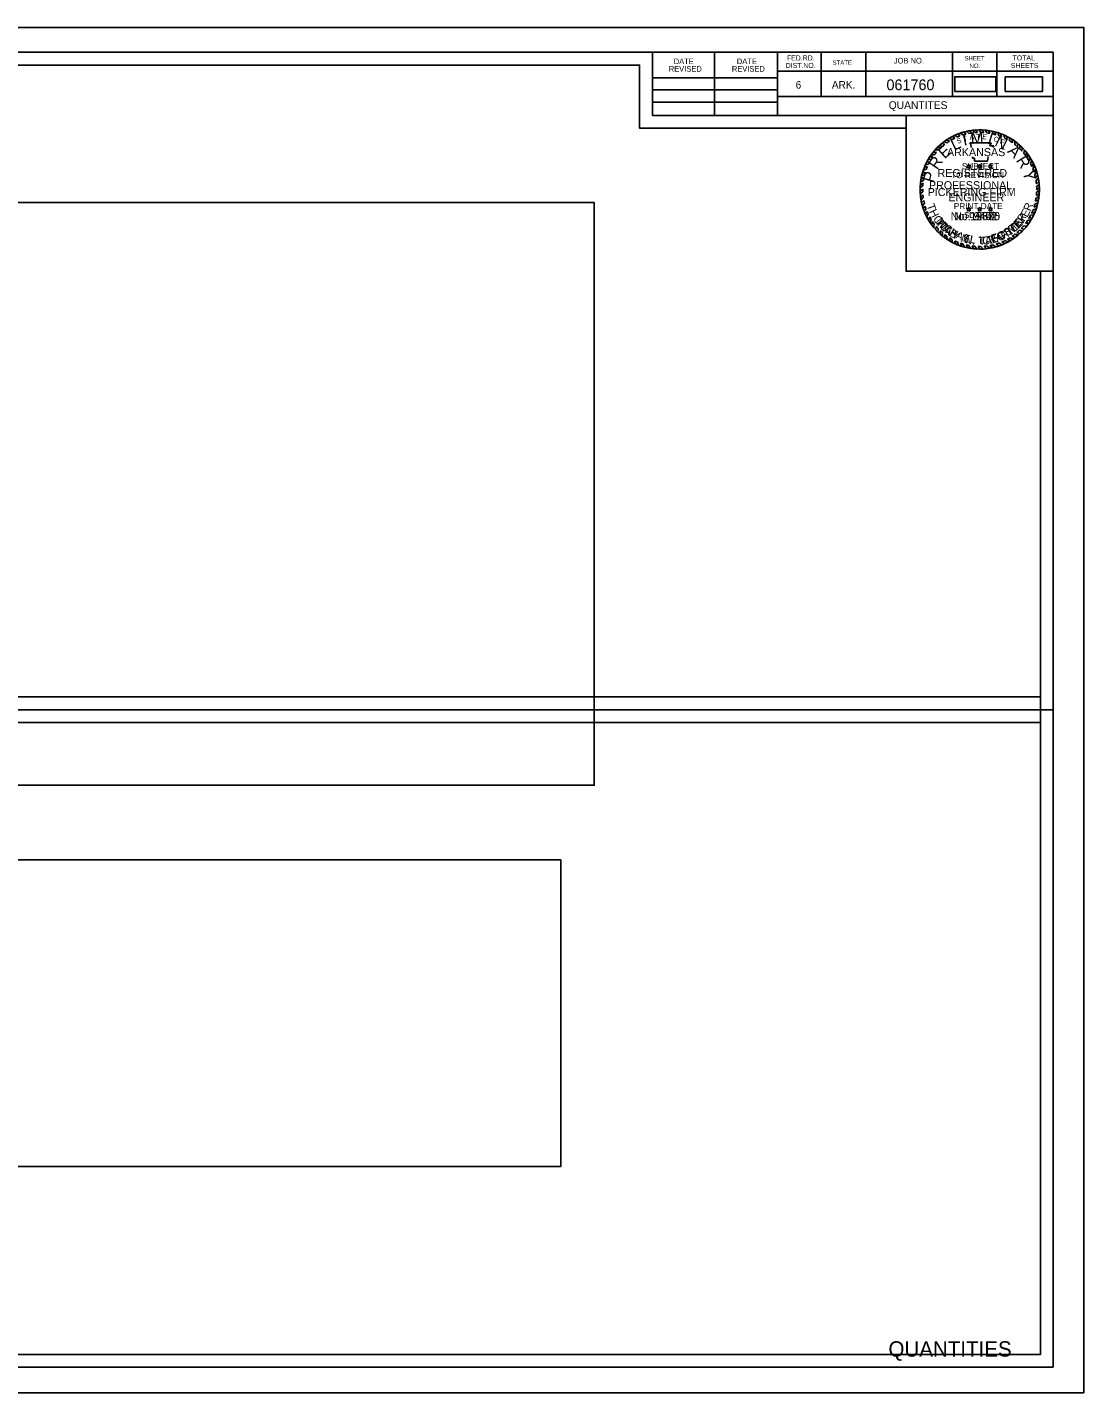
# Model space of a CAD drawing. Extents: x 365 to 1553, y -4 to 209.
# Drawn here: x 532.8 to 697.9, y -4 to 209.4 of the extents above; entities that cross this region are included whole.
import ezdxf

# ---------------------------------------------------------------- set-up
doc = ezdxf.new("R2010")
doc.units = 0
for name, color, linetype in [('Default', 7, 'Continuous'), ('R_Border', 7, 'Continuous'), ('R_Border Notes', 7, 'Continuous'), ('R_Border Plan-Plan', 7, 'Continuous'), ('R_Border Title', 7, 'Continuous'), ('R_No Plot', 7, 'Continuous'), ('STAMP_PE_CRAFTON', 7, 'Continuous'), ('STAMP_PE_FOSTER', 7, 'Continuous'), ('STAMP_PE_SEAL-INFO', 7, 'Continuous'), ('STAMP_PE_TAEGTMEYER', 7, 'Continuous'), ('STAMP_PE_TXT', 7, 'Continuous'), ('STAMP_PRELIMINARY', 7, 'Continuous')]:
    doc.layers.add(name, color=color, linetype=linetype)

msp = doc.modelspace()

# ---------------------------------------------------------------- linework, layer by layer
at = {"layer": 'Default'}
for points in [[(677.71, 199.3), (684.15, 199.3), (684.15, 201.61), (677.71, 201.61)], [(685.6, 199.3), (691.43, 199.3), (691.43, 201.61), (685.6, 201.61)], [(452.83, 90.94), (621.39, 90.94), (621.39, 181.97), (452.83, 181.97)], [(458.06, 31.38), (616.17, 31.38), (616.17, 79.26), (458.06, 79.26)]]:
    msp.add_lwpolyline(points, close=True, dxfattribs=at)
at = {"layer": 'R_Border'}
for p, q in [((376.94, 205.46), (693.12, 205.46)), ((630.48, 195.58), (630.48, 205.46)), ((640.16, 195.58), (640.16, 205.46)), ((650.02, 205.46), (650.02, 195.58)), ((656.86, 205.46), (656.86, 198.52)), ((663.8, 205.46), (663.8, 198.52)), ((677.38, 205.46), (677.38, 198.52)), ((684.32, 205.46), (684.32, 198.52)), ((693.12, 0), (693.12, 205.46)), ((630.48, 201.44), (650.02, 201.44)), ((693.12, 202.52), (650.02, 202.52)), ((693.12, 202.54), (693.12, 202.54)), ((630.48, 199.58), (650.02, 199.58)), ((693.12, 198.52), (650.02, 198.52)), ((652.98, 198.52), (693.12, 198.52)), ((630.48, 197.64), (650.02, 197.64)), ((693.12, 195.58), (630.48, 195.58)), ((693.12, 0), (376.94, 0))]:
    msp.add_line(p, q, dxfattribs=at)
at = {"layer": 'R_Border Plan-Plan'}
msp.add_line((376.94, 102.73), (693.12, 102.73), dxfattribs=at)
at = {"layer": 'R_No Plot'}
for points in [[(364.53, 209.35), (697.87, 209.35), (697.87, -3.98), (364.53, -3.98)], [(691.12, 104.73), (378.94, 104.73), (378.94, 203.46), (628.48, 203.46), (628.48, 193.58), (646.02, 193.58), (670.12, 193.58), (670.12, 171.25), (691.12, 171.25)], [(378.94, 203.46), (628.48, 203.46), (628.48, 193.58), (646.02, 193.58), (670.12, 193.58), (670.12, 171.25), (691.12, 171.25), (691.12, 2), (378.94, 2)], [(670.12, 195.58), (693.12, 195.58), (693.12, 171.25), (670.12, 171.25)], [(378.94, 100.73), (691.12, 100.73), (691.12, 2), (378.94, 2)]]:
    msp.add_lwpolyline(points, close=True, dxfattribs=at)
at = {"layer": 'STAMP_PE_SEAL-INFO'}
for p, q in [((676.84, 192.03), (677.27, 191.81)), ((677.29, 192.28), (677.75, 192.06)), ((677.72, 192.49), (678.11, 192.22)), ((678.23, 192.71), (678.52, 192.38)), ((678.58, 192.84), (678.96, 192.53)), ((679.17, 193.02), (679.45, 192.67)), ((679.55, 193.11), (679.91, 192.77)), ((680.04, 193.21), (680.34, 192.84)), ((680.55, 193.28), (680.83, 192.9)), ((681.29, 192.93), (680.98, 193.32)), ((681.79, 192.93), (681.51, 193.34)), ((682.24, 192.91), (681.99, 193.34)), ((682.75, 192.86), (682.46, 193.31)), ((683.18, 192.8), (682.92, 193.25)), ((683.74, 192.68), (683.56, 193.14)), ((684.14, 192.57), (683.98, 193.04)), ((684.59, 192.42), (684.45, 192.9)), ((685.01, 192.26), (684.87, 192.76)), ((685.47, 192.06), (685.37, 192.56)), ((685.92, 191.83), (685.83, 192.34)), ((686.3, 191.6), (686.26, 192.1)), ((674.66, 190.22), (675.18, 190.19)), ((674.98, 190.57), (675.52, 190.53)), ((675.31, 190.89), (675.77, 190.75)), ((675.66, 191.19), (676.19, 191.09)), ((676.03, 191.52), (676.49, 191.31)), ((676.45, 191.79), (676.9, 191.58)), ((680.09, 191.31), (683.43, 191.31)), ((680.21, 191.01), (680.09, 191.31)), ((680.31, 190.71), (680.21, 191.01)), ((680.32, 190.59), (680.31, 190.71)), ((683.43, 191.31), (683.21, 190.82)), ((683.21, 190.82), (683.84, 190.82)), ((683.84, 190.82), (683.7, 190.59)), ((686.74, 191.32), (686.71, 191.83)), ((687.1, 191.05), (687.13, 191.54)), ((687.55, 190.68), (687.57, 191.2)), ((687.86, 190.39), (687.93, 190.88)), ((688.22, 190.01), (688.28, 190.54)), ((688.49, 189.7), (688.63, 190.17)), ((673.13, 187.89), (673.63, 187.99)), ((673.32, 188.27), (673.82, 188.34)), ((673.55, 188.7), (674.04, 188.72)), ((673.8, 189.1), (674.31, 189.13)), ((674.03, 189.44), (674.54, 189.44)), ((674.31, 189.81), (674.86, 189.83)), ((680.51, 188.89), (680.49, 189.1)), ((680.83, 188.89), (680.51, 188.89)), ((680.83, 188.46), (680.83, 188.89)), ((682.86, 188.46), (680.83, 188.46)), ((682.87, 188.79), (682.86, 188.46)), ((682.95, 189.1), (682.87, 188.79)), ((688.82, 189.28), (688.95, 189.78)), ((689.04, 188.96), (689.21, 189.43)), ((689.34, 188.47), (689.53, 188.96)), ((689.54, 188.1), (689.77, 188.54)), ((689.77, 187.62), (690, 188.1)), ((672.9, 185.89), (672.44, 185.64)), ((672.54, 186.14), (673.01, 186.33)), ((672.64, 186.54), (673.12, 186.71)), ((672.8, 187.05), (673.28, 187.18)), ((672.95, 187.45), (673.45, 187.6)), ((689.91, 187.28), (690.18, 187.71)), ((690.11, 186.73), (690.38, 187.2)), ((690.22, 186.37), (690.51, 186.82)), ((690.35, 185.81), (690.67, 186.25)), ((690.42, 185.43), (690.77, 185.78)), ((672.72, 184.57), (672.3, 184.31)), ((672.7, 184.08), (672.3, 183.74)), ((672.76, 185), (672.32, 184.71)), ((672.71, 183.67), (672.32, 183.35)), ((672.82, 185.43), (672.37, 185.21)), ((690.49, 184.92), (690.86, 185.25)), ((690.52, 184.5), (690.91, 184.79)), ((690.52, 183.58), (690.94, 183.85)), ((690.53, 183.98), (690.94, 184.3)), ((672.74, 183.18), (672.37, 182.82)), ((672.8, 182.75), (672.44, 182.37)), ((672.87, 182.29), (672.53, 181.92)), ((672.97, 181.87), (672.66, 181.45)), ((673.09, 181.42), (672.8, 181)), ((690.08, 181.24), (690.57, 181.44)), ((690.23, 181.73), (690.7, 181.93)), ((690.34, 182.18), (690.79, 182.38)), ((690.43, 182.68), (690.87, 182.9)), ((690.48, 183.07), (690.91, 183.33)), ((673.23, 181), (672.95, 180.59)), ((673.4, 180.57), (673.14, 180.15)), ((673.57, 180.19), (673.34, 179.73)), ((673.8, 179.73), (673.61, 179.24)), ((674.04, 179.33), (673.86, 178.86)), ((689.13, 179.23), (689.61, 179.22)), ((689.3, 179.51), (689.8, 179.56)), ((689.57, 180), (690.06, 180.07)), ((689.73, 180.34), (690.22, 180.44)), ((689.95, 180.86), (690.43, 180.99)), ((674.24, 179.01), (674.13, 178.46)), ((674.52, 178.62), (674.42, 178.09)), ((674.83, 178.25), (674.74, 177.73)), ((675.13, 177.91), (675.07, 177.39)), ((675.45, 177.58), (675.42, 177.05)), ((675.8, 177.27), (675.79, 176.74)), ((687.44, 177.27), (687.91, 177.14)), ((687.84, 177.64), (688.28, 177.51)), ((688.1, 177.9), (688.58, 177.82)), ((688.48, 178.34), (688.94, 178.26)), ((688.79, 178.73), (689.29, 178.73)), ((676.16, 176.98), (676.18, 176.45)), ((676.5, 176.73), (676.53, 176.21)), ((676.92, 176.45), (676.98, 175.93)), ((677.27, 176.24), (677.36, 175.73)), ((677.75, 175.99), (677.91, 175.47)), ((678.13, 175.82), (678.3, 175.31)), ((678.62, 175.63), (678.83, 175.13)), ((679.03, 175.49), (679.25, 175)), ((679.54, 175.36), (679.75, 174.89)), ((679.93, 175.27), (680.18, 174.81)), ((680.43, 175.19), (680.67, 174.75)), ((680.87, 175.14), (681.15, 174.71)), ((681.36, 175.11), (681.66, 174.7)), ((681.82, 175.11), (682.16, 174.72)), ((682.33, 175.14), (682.66, 174.76)), ((682.77, 175.18), (683.15, 174.83)), ((683.22, 175.25), (683.61, 174.91)), ((683.71, 175.36), (684.09, 175.03)), ((684.17, 175.48), (684.59, 175.19)), ((684.66, 175.65), (685.1, 175.38)), ((685.08, 175.81), (685.5, 175.55)), ((685.54, 176.02), (686.02, 175.81)), ((685.95, 176.23), (686.37, 176)), ((686.36, 176.48), (686.81, 176.28)), ((686.71, 176.71), (687.15, 176.52)), ((687.17, 177.05), (687.64, 176.9))]:
    msp.add_line(p, q, dxfattribs=at)
for radius, start, end in [(9.32, 117.6544, 120.8099), (8.91, 115.6869, 119.1583), (9.32, 111.3124, 114.7026), (8.91, 110.3086, 113.1659), (9.32, 105.2339, 109.0352), (8.91, 104.0352, 107.3615), (9.32, 99.7525, 102.7765), (8.91, 98.258, 101.0329), (9.32, 93.9381, 96.5517), (8.91, 92.1102, 95.0367), (9.32, 87.7298, 90.6707), (8.91, 85.9628, 88.9097), (9.32, 81.9732, 84.8236), (8.91, 79.9264, 82.696), (9.32, 75.3125, 77.9426), (8.91, 73.5575, 76.2314), (9.32, 69.6061, 72.3058), (8.91, 67.6248, 70.504), (9.32, 63.1329, 66.2704), (8.91, 61.1558, 64.3784), (9.32, 56.9003, 60.0942), (9.32, 135.4021, 138.3031), (8.91, 133.1331, 136.2562), (9.32, 129.7326, 132.5376), (8.91, 127.5297, 130.9683), (9.32, 123.6199, 126.5906), (8.91, 121.9746, 125.11), (8.91, 54.9238, 58.2702), (8.91, 48.3016, 52.0395), (9.32, 50.3492, 53.7159), (8.91, 42.2212, 45.5512), (9.32, 44.3405, 47.3929), (9.32, 38.1247, 41.2316), (9.32, 152.864, 155.5189), (9.32, 147.0072, 149.899), (8.91, 151.0315, 153.573), (9.32, 141.6056, 144.4486), (8.91, 145.0197, 148.2104), (8.91, 139.301, 142.5873), (8.91, 36.135, 39.5311), (8.91, 29.9032, 33.6645), (9.32, 31.9614, 35.4294), (8.91, 23.7732, 27.2211), (9.32, 25.9391, 29.0125), (9.32, 170.0003, 172.6878), (9.32, 164.3068, 166.894), (9.32, 158.4077, 161.0701), (8.91, 167.9048, 170.9039), (8.91, 162.4331, 165.0013), (8.91, 156.3402, 159.2319), (8.91, 17.6802, 21.4251), (9.32, 19.9538, 23.3141), (8.91, 11.5444, 15.2364), (9.32, 13.8421, 17.4447), (9.32, 7.5852, 10.8621), (9.32, 175.7409, 178.2066), (9.32, 181.7251, 184.1626), (8.91, 179.6454, 182.2633), (8.91, 173.73, 176.4734), (8.91, 5.7599, 9.0606), (8.91, 353.8632, 357.1274), (8.91, 359.7329, 3.0639), (9.32, 1.7215, 4.7268), (9.32, 355.7156, 358.9569), (9.32, 187.4204, 190.1927), (9.32, 193.0369, 195.9973), (8.91, 185.4539, 188.234), (8.91, 191.2274, 193.9858), (8.91, 196.9675, 199.8353), (8.91, 341.777, 345.0925), (8.91, 348.0778, 351.3435), (9.32, 343.8925, 347.035), (9.32, 349.8305, 353.0885), (9.32, 198.8967, 201.6281), (9.32, 204.5479, 207.4328), (8.91, 202.7761, 205.4791), (9.32, 210.8636, 213.6571), (8.91, 208.7883, 211.7934), (8.91, 323.5851, 327.4407), (9.32, 325.4405, 328.9872), (8.91, 329.5549, 333.2076), (8.91, 335.6038, 339.1858), (9.32, 331.4037, 334.9332), (9.32, 337.3837, 340.9933), (9.32, 216.6115, 219.491), (8.91, 214.1838, 217.2747), (9.32, 222.48, 225.3801), (8.91, 220.3909, 223.3056), (8.91, 226.2494, 229.2407), (8.91, 310.7744, 314.3161), (9.32, 312.4518, 315.6633), (8.91, 316.6531, 320.3711), (9.32, 318.2846, 321.8043), (9.32, 228.3665, 231.348), (8.91, 232.229, 234.9336), (9.32, 234.295, 236.9452), (8.91, 238.2223, 240.8353), (9.32, 240.1977, 242.8613), (8.91, 244.3204, 246.9486), (9.32, 246.576, 249.1558), (8.91, 250.3491, 253.1216), (9.32, 252.5967, 255.3252), (8.91, 256.505, 259.1192), (8.91, 262.3783, 265.2012), (8.91, 268.3215, 271.277), (8.91, 274.6157, 277.4486), (8.91, 280.3459, 283.5814), (9.32, 282.3199, 285.3702), (8.91, 286.6423, 289.9783), (9.32, 288.5709, 291.9733), (8.91, 292.8745, 296.1185), (9.32, 294.6481, 298.2166), (8.91, 299.0768, 302.1724), (9.32, 300.621, 303.8703), (8.91, 304.823, 308.5143), (9.32, 306.3721, 310.208), (9.32, 258.4433, 261.1398), (9.32, 264.1978, 267.1009), (9.32, 270.2548, 273.3361), (9.32, 276.4239, 279.4357)]:
    msp.add_arc((681.62, 184.02), radius, start, end, dxfattribs=at)
at = {"layer": 'STAMP_PE_TXT'}
for p, q in [((679.8, 187.59), (679.6, 187.74)), ((679.6, 187.74), (679.84, 187.74)), ((679.84, 187.74), (679.92, 187.97)), ((679.92, 187.97), (679.99, 187.74)), ((679.99, 187.74), (680.24, 187.74)), ((680.24, 187.74), (680.04, 187.59)), ((681.49, 187.59), (681.3, 187.74)), ((681.3, 187.74), (681.54, 187.74)), ((681.54, 187.74), (681.62, 187.97)), ((681.62, 187.97), (681.69, 187.74)), ((681.69, 187.74), (681.94, 187.74)), ((681.94, 187.74), (681.74, 187.59)), ((683.19, 187.59), (682.99, 187.74)), ((682.99, 187.74), (683.24, 187.74)), ((683.24, 187.74), (683.31, 187.97)), ((683.31, 187.97), (683.39, 187.74)), ((683.39, 187.74), (683.64, 187.74)), ((683.64, 187.74), (683.44, 187.59)), ((679.72, 187.36), (679.8, 187.59)), ((679.92, 187.5), (679.72, 187.36)), ((680.12, 187.36), (679.92, 187.5)), ((680.04, 187.59), (680.12, 187.36)), ((681.42, 187.36), (681.49, 187.59)), ((681.62, 187.5), (681.42, 187.36)), ((681.82, 187.36), (681.62, 187.5)), ((681.74, 187.59), (681.82, 187.36)), ((683.12, 187.36), (683.19, 187.59)), ((683.31, 187.5), (683.12, 187.36)), ((683.51, 187.36), (683.31, 187.5)), ((683.44, 187.59), (683.51, 187.36)), ((679.8, 180.89), (679.6, 181.03)), ((679.6, 181.03), (679.84, 181.03)), ((679.72, 180.65), (679.8, 180.89)), ((679.92, 180.8), (679.72, 180.65)), ((679.84, 181.03), (679.92, 181.26)), ((679.92, 181.26), (679.99, 181.03)), ((680.12, 180.65), (679.92, 180.8)), ((679.99, 181.03), (680.24, 181.03)), ((680.24, 181.03), (680.04, 180.89)), ((680.04, 180.89), (680.12, 180.65)), ((681.49, 180.89), (681.3, 181.03)), ((681.3, 181.03), (681.54, 181.03)), ((681.42, 180.65), (681.49, 180.89)), ((681.62, 180.8), (681.42, 180.65)), ((681.54, 181.03), (681.62, 181.26)), ((681.62, 181.26), (681.69, 181.03)), ((681.82, 180.65), (681.62, 180.8)), ((681.69, 181.03), (681.94, 181.03)), ((681.94, 181.03), (681.74, 180.89)), ((681.74, 180.89), (681.82, 180.65)), ((683.19, 180.89), (682.99, 181.03)), ((682.99, 181.03), (683.24, 181.03)), ((683.12, 180.65), (683.19, 180.89)), ((683.31, 180.8), (683.12, 180.65)), ((683.24, 181.03), (683.31, 181.26)), ((683.31, 181.26), (683.39, 181.03)), ((683.51, 180.65), (683.31, 180.8)), ((683.39, 181.03), (683.64, 181.03)), ((683.64, 181.03), (683.44, 180.89)), ((683.44, 180.89), (683.51, 180.65))]:
    msp.add_line(p, q, dxfattribs=at)
at = {"layer": 'STAMP_PRELIMINARY'}
msp.add_circle((681.62, 184.02), 9.32, dxfattribs=at)

# ---------------------------------------------------------------- texts
at = {"layer": 'R_Border'}
for s, height, p in [('FED.RD.', 0.782, (651.5, 204.18)), ('SHEET', 0.684, (679.24, 204.18)), ('TOTAL', 0.782, (686.76, 204.18)), ('REVISED', 0.879, (633.03, 202.42)), ('DATE', 0.879, (633.81, 203.6)), ('REVISED', 0.879, (642.89, 202.42)), ('DATE', 0.879, (643.67, 203.6)), ('DIST.NO.', 0.782, (651.3, 203)), ('STATE', 0.684, (658.62, 203.5)), ('JOB NO.', 0.879, (668.2, 203.7)), ('NO.', 0.684, (680.02, 203)), ('SHEETS', 0.782, (686.48, 203)), ('6', 1.17, (652.86, 199.78)), ('ARK.', 1.172, (658.52, 199.78))]:
    msp.add_text(s, height=height, dxfattribs=at).set_placement(p)
at = {"layer": 'R_Border Notes'}
for s, height, p in [('061760', 1.68, (667.05, 199.53)), ('QUANTITES', 1.2, (667.4, 196.6))]:
    msp.add_text(s, height=height, dxfattribs=at).set_placement(p)
at = {"layer": 'R_Border Title'}
msp.add_text('QUANTITIES', height=2.4, dxfattribs=at).set_placement((667.36, 1.65))
at = {"layer": 'STAMP_PE_CRAFTON'}
for s, rotation, p in [('T', 310.7442, (674.58, 178.92)), ('N', 49.2411, (687.9, 178.04)), ('O', 317.6422, (675.25, 178.11)), ('N', 324.4537, (676.1, 177.32)), ('Y', 331.1686, (677.13, 176.61)), ('A', 20.5125, (684.3, 175.78)), ('F', 28.7821, (685.28, 176.15)), ('T', 34.1136, (686.19, 176.66)), ('O', 41.8391, (687.05, 177.26)), ('N', 347.4752, (679.18, 175.69)), ('.', 356.8926, (680.41, 175.41)), ('C', 6.0117, (682.09, 175.36)), ('R', 14.8189, (683.18, 175.48))]:
    msp.add_text(s, height=1.25, rotation=rotation, dxfattribs=at).set_placement(p)
msp.add_text('No. 12370', height=1.25, dxfattribs=at).set_placement((677.08, 179.22))
at = {"layer": 'STAMP_PE_FOSTER'}
for s, rotation, p in [('M', 308.339, (674.73, 179.04)), ('E', 46.9613, (687.62, 178.01)), ('R', 54.5031, (688.34, 178.83)), ('I', 314.1842, (675.53, 178.11)), ('C', 319.8733, (675.88, 177.75)), ('H', 327.7235, (676.81, 177.02)), ('A', 335.7276, (677.79, 176.44)), ('E', 343.5779, (678.93, 175.97)), ('F', 15.8691, (683.65, 175.78)), ('O', 23.719, (684.7, 176.1)), ('S', 31.7234, (685.81, 176.63)), ('T', 39.4194, (686.76, 177.26)), ('L', 350.8115, (679.99, 175.69)), ('L', 1.2666, (681.53, 175.53)), ('.', 6.8035, (682.58, 175.59))]:
    msp.add_text(s, height=1.2, rotation=rotation, dxfattribs=at).set_placement(p)
msp.add_text('No. 9402', height=1.25, dxfattribs=at).set_placement((677.6, 179.22))
at = {"layer": 'STAMP_PE_TAEGTMEYER'}
for s, rotation, p in [('T', 289.646, (673.31, 181.53)), ('R', 69.57, (689.56, 180.54)), ('H', 296.7339, (673.67, 180.55)), ('O', 303.7708, (674.26, 179.44)), ('M', 314.2033, (674.92, 178.49)), ('E', 46.8094, (687.66, 177.8)), ('Y', 53.9986, (688.39, 178.61)), ('E', 63.0984, (689.06, 179.56)), ('A', 321.0594, (675.88, 177.52)), ('S', 327.8239, (676.71, 176.88)), ('G', 23.3052, (684.62, 175.88)), ('T', 31.466, (685.72, 176.38)), ('M', 39.3, (686.61, 176.92)), ('N', 344.2727, (678.6, 175.87)), ('.', 350.6464, (679.82, 175.54)), ('T', 3.0061, (681.48, 175.34)), ('A', 8.9826, (682.53, 175.4)), ('E', 17.6836, (683.57, 175.55))]:
    msp.add_text(s, height=1.25, rotation=rotation, dxfattribs=at).set_placement(p)
msp.add_text('No. 19605', height=1.25, dxfattribs=at).set_placement((677.08, 179.22))
at = {"layer": 'STAMP_PE_TXT'}
for s, rotation, p in [('S', 23.5541, (678.22, 191.13)), ('T', 16.311, (679.14, 191.5)), ('A', 9.0679, (680.1, 191.75)), ('T', 1.8248, (681.09, 191.88)), ('E', 355.2002, (682, 191.89)), ('O', 342.2506, (683.72, 191.61)), ('F', 335.0075, (684.69, 191.27))]:
    msp.add_text(s, height=0.781, rotation=rotation, dxfattribs=at).set_placement(p)
for s, p in [('ARKANSAS', (676.51, 189.23)), ('REGISTERED', (675.03, 185.96)), ('PROFESSIONAL', (673.69, 184.06)), ('ENGINEER', (676.73, 182.16))]:
    msp.add_text(s, height=1.25, dxfattribs=at).set_placement(p)
at = {"layer": 'STAMP_PRELIMINARY'}
for s, rotation, p in [('I', 12.5248, (679.15, 190.81)), ('M', 3.1074, (680.25, 191.12)), ('I', 342.3164, (682.72, 191.19)), ('N', 333.9382, (683.83, 190.91)), ('E', 42.3578, (676.14, 188.72)), ('L', 25.513, (677.63, 190.05)), ('A', 315.6579, (685.86, 189.89)), ('R', 56.2292, (674.99, 186.99)), ('R', 301.3831, (687.23, 188.57)), ('P', 73.913, (674.44, 184.96)), ('Y', 283.2593, (688.32, 186.79))]:
    msp.add_text(s, height=1.8, rotation=rotation, dxfattribs=at).set_placement(p)
for s, height, p in [('SUBJECT', 0.96, (678.82, 187.17)), ('TO REVISION', 0.96, (677.15, 185.79)), ('PICKERING FIRM', 1.25, (673.49, 182.99)), ('PRINT DATE', 0.96, (677.57, 180.94)), ('$DATE$', 0.96, (679.25, 179.55))]:
    msp.add_text(s, height=height, dxfattribs=at).set_placement(p)

doc.saveas('drawing.dxf')
